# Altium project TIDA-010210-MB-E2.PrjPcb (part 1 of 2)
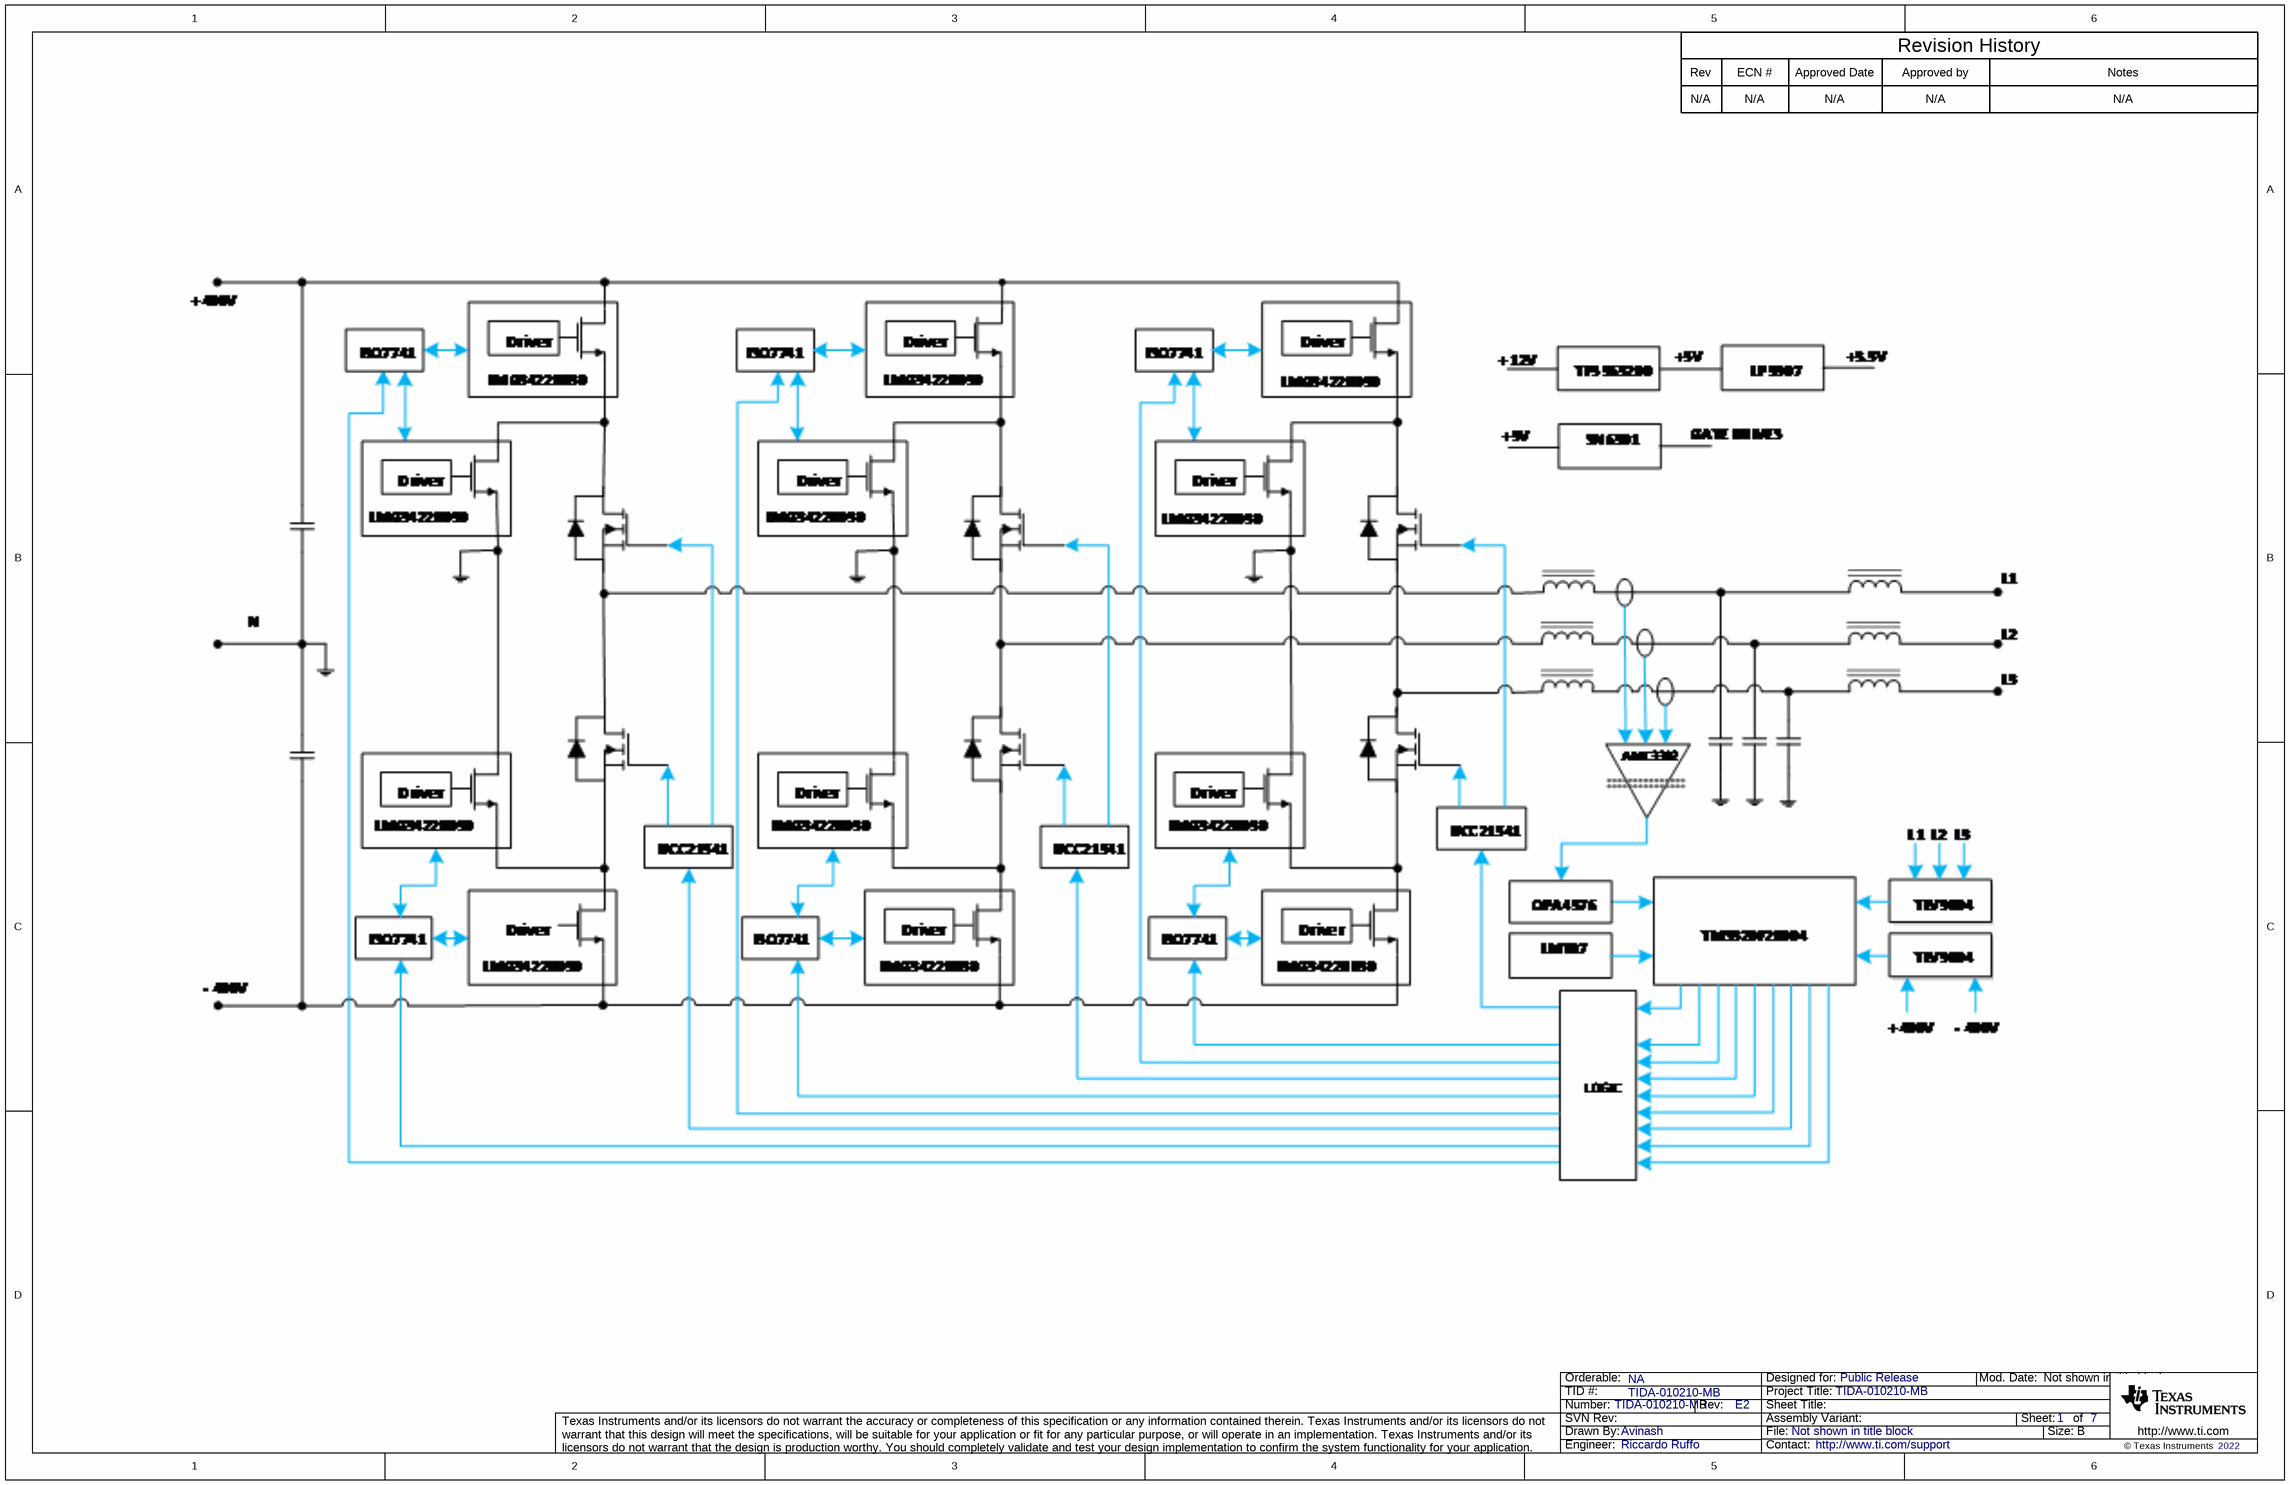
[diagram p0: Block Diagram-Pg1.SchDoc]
TID: TIDA-010210-MB; TechSupport: http://www.ti.com/support; SCH_Rev: E2; PRJ_Title: TIDA-010210-MB; PRJ_Number: TIDA-010210-MB; PRJ_Engineer: Riccardo Ruffo; PRJ_Customer: Public Release; PCB_Rev: E2; PCB_Layout: Riccardo Ruffo; EVM_Orderable: NA; CopyrightYear: 2022
7 sheets, 474 parts. Net scope: global (net labels, ports and power ports of the same name join across sheets).
Board file: TIDA-010210-MB-E2.PcbDoc
Sheets:
  Block Diagram-Pg1.SchDoc
  Power Stage-Pg2.SchDoc
  Power Supply and Protection-Pg3.SchDoc
  Voltage Sensing-Pg4.SchDoc
  Current Sensing-Pg5.SchDoc
  Controller Card-Pg6.SchDoc
  Hardware-Pg7.SchDoc

## Sheet Block Diagram-Pg1.SchDoc
size 431 x 279 mm; Date: Not shown in title block; ApprovedBy: Not shown in title block; CheckedBy: Not shown in title block; Author: Not shown in title block; CompanyName: Not shown in title block; DrawnBy: Avinash; Engineer: Not shown in title block; Organization: Not shown in title block; Address1: Not shown in title block; Address2: Not shown in title block; Address3: Not shown in title block; Address4: Not shown in title block; DocumentNumber: 1; Revision: Use project parameter SCH_Rev; SheetNumber: 1; SheetTotal: 7; PageSetup: Record=PageOptions¦CenterHorizontal=True¦CenterVertical=True¦PrintScale=1.00¦XCorrection=1.00¦YCorrection=1.00¦PrintKind=0¦BorderSize=5000000¦LeftOffset=0¦BottomOffset=0¦Orientation=2¦PaperLength=1000¦PaperWidth=1000¦Scale=100¦PaperSource=15¦PrintQuality=600¦MediaType=1¦DitherType=10¦PaperKind=Letter¦PrintScaleMode=1

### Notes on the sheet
- Rev
- N/A
- ECN #
- Approved Date
- Approved by
- Revision History
- Notes

## Sheet Power Stage-Pg2.SchDoc
size 431 x 279 mm; Date: Not shown in title block; ApprovedBy: Not shown in title block; CheckedBy: Not shown in title block; Author: Not shown in title block; CompanyName: Not shown in title block; DrawnBy: Avinash; Engineer: Not shown in title block; Organization: Not shown in title block; Address1: Not shown in title block; Address2: Not shown in title block; Address3: Not shown in title block; Address4: Not shown in title block; DocumentNumber: 1; Revision: Use project parameter SCH_Rev; SheetNumber: 2; SheetTotal: 7; PageSetup: Record=PageOptions¦CenterHorizontal=True¦CenterVertical=True¦PrintScale=1.00¦XCorrection=1.00¦YCorrection=1.00¦PrintKind=0¦BorderSize=5000000¦LeftOffset=0¦BottomOffset=0¦Orientation=2¦PaperLength=1000¦PaperWidth=1000¦Scale=100¦PaperSource=15¦PrintQuality=600¦MediaType=1¦DitherType=10¦PaperKind=Letter¦PrintScaleMode=1
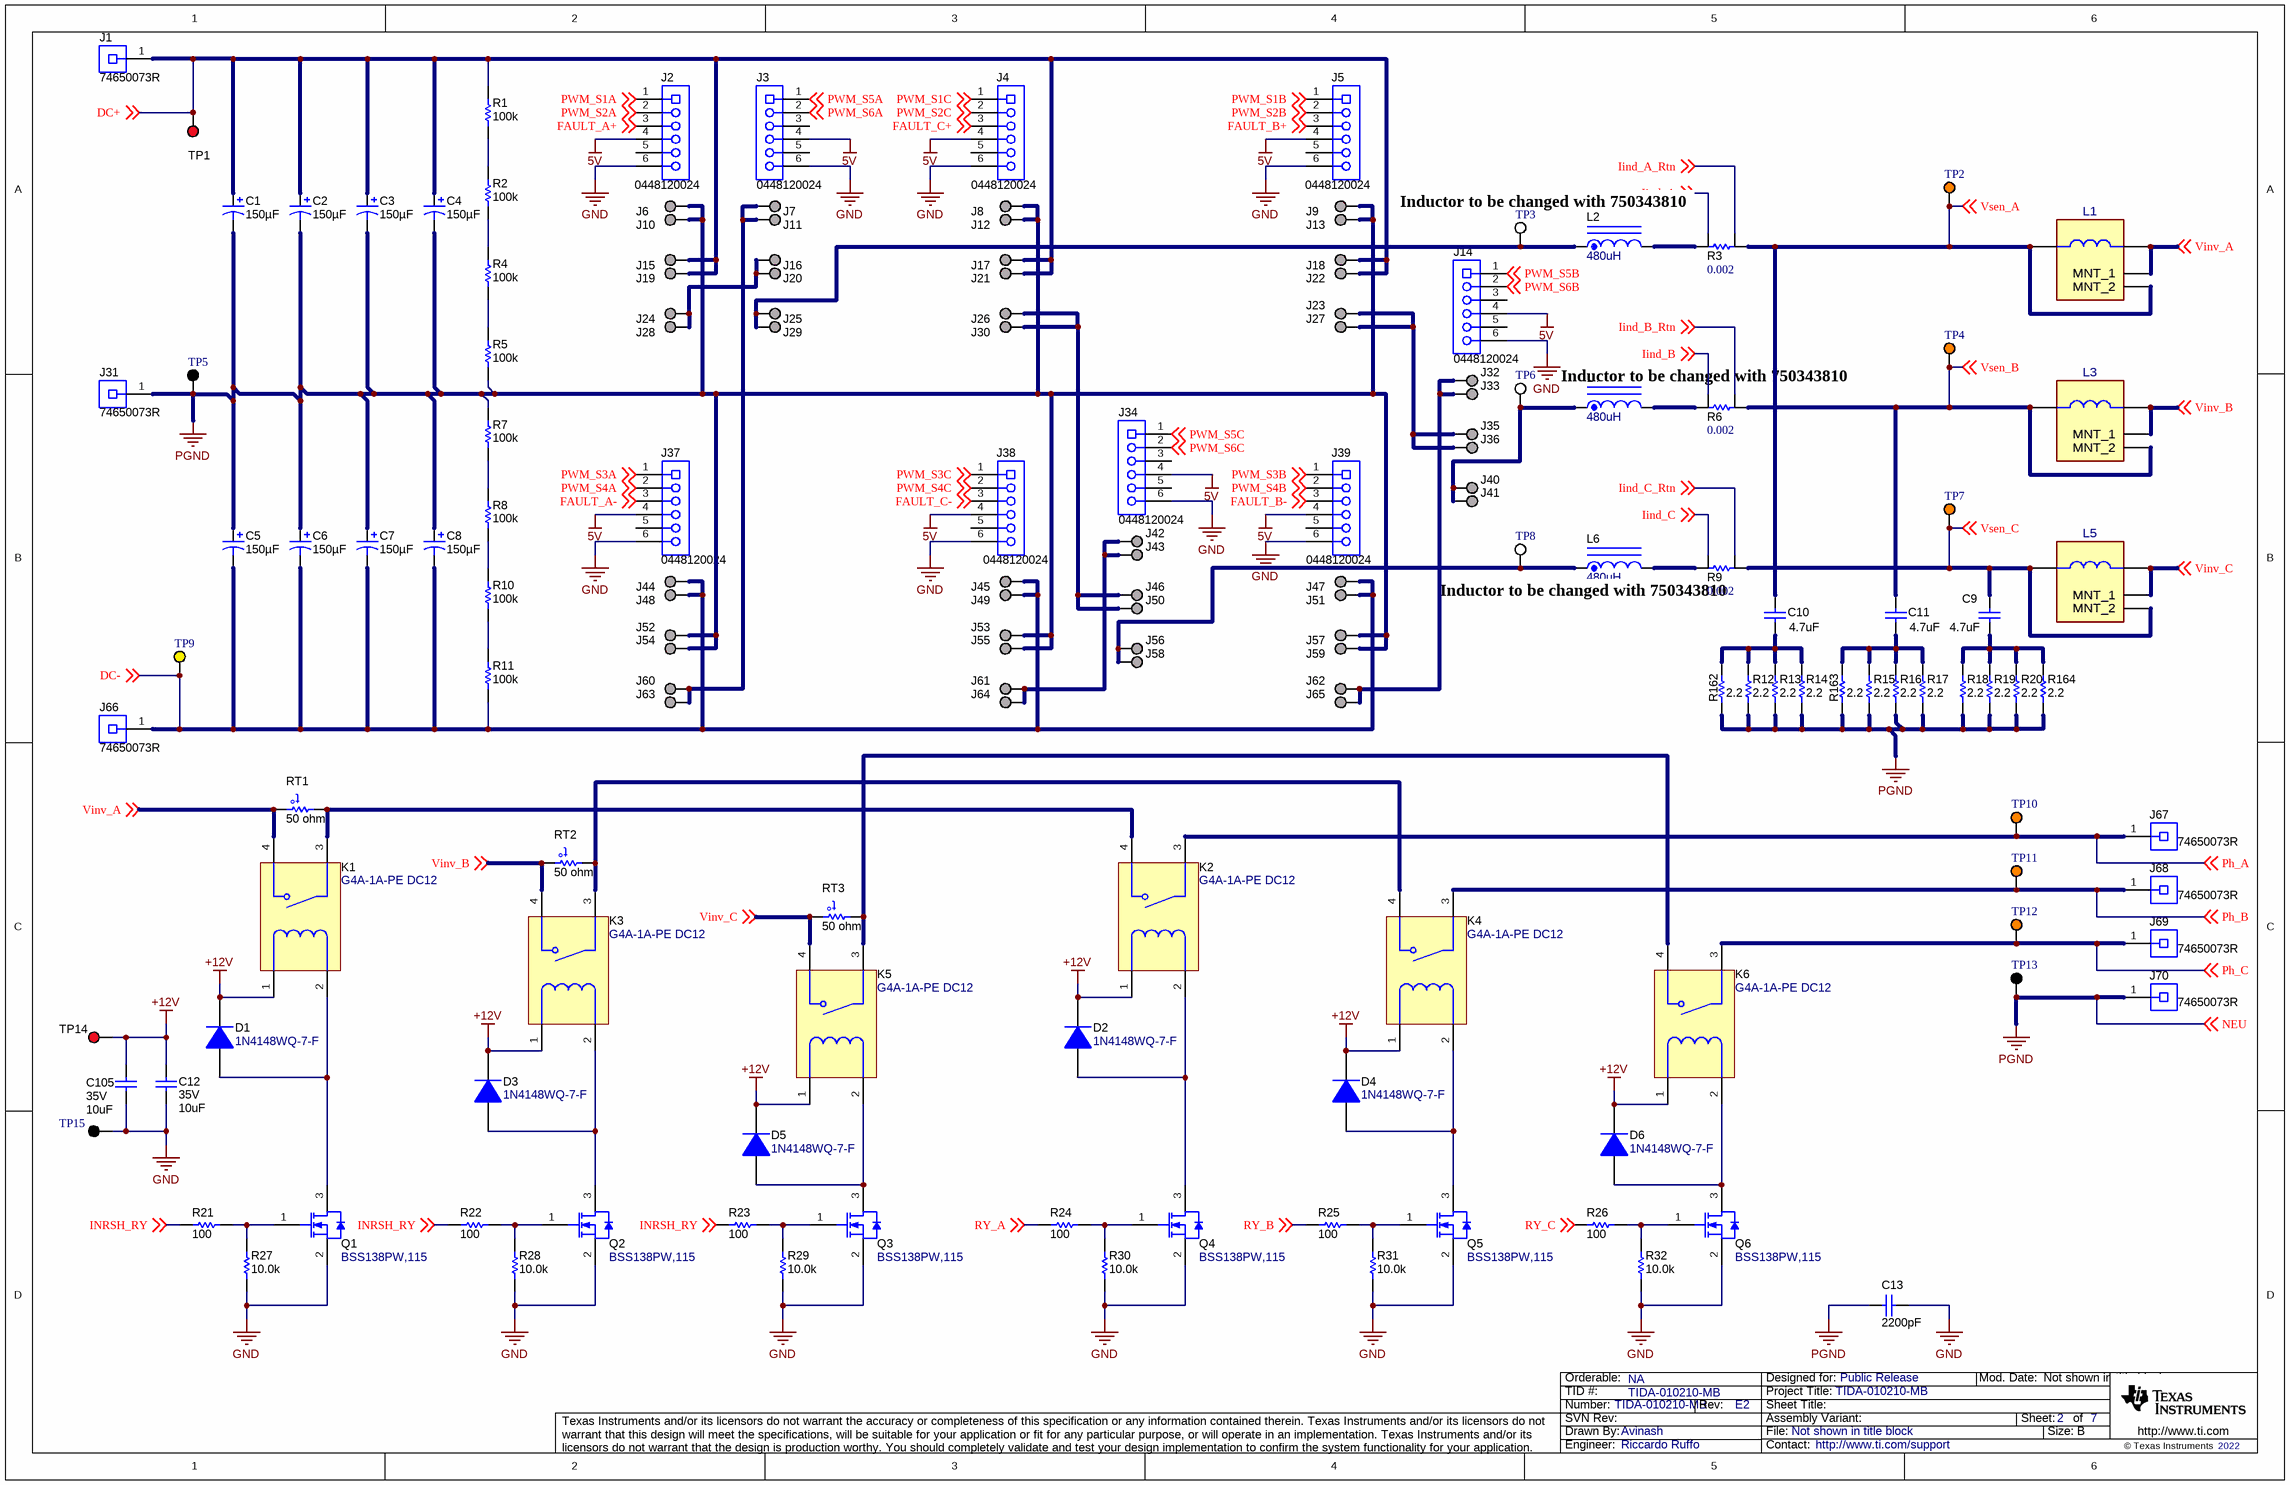
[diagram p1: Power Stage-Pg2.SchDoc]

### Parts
C1  ValueDisplayed: 150µF  [ESG157M500AQ5]  (hidden comment: ESG157M500AQ5)
C2  ValueDisplayed: 150µF  [ESG157M500AQ5]  (hidden comment: ESG157M500AQ5)
C3  ValueDisplayed: 150µF  [ESG157M500AQ5]  (hidden comment: ESG157M500AQ5)
C4  ValueDisplayed: 150µF  [ESG157M500AQ5]  (hidden comment: ESG157M500AQ5)
C5  ValueDisplayed: 150µF  [ESG157M500AQ5]  (hidden comment: ESG157M500AQ5)
C6  ValueDisplayed: 150µF  [ESG157M500AQ5]  (hidden comment: ESG157M500AQ5)
C7  ValueDisplayed: 150µF  [ESG157M500AQ5]  (hidden comment: ESG157M500AQ5)
C8  ValueDisplayed: 150µF  [ESG157M500AQ5]  (hidden comment: ESG157M500AQ5)
C9  ValueDisplayed: 4.7uF  [B32924_31mm]  (hidden comment: B32924D3475K)
C10  ValueDisplayed: 4.7uF  [B32924_31mm]  (hidden comment: B32924D3475K)
C11  ValueDisplayed: 4.7uF  [B32924_31mm]  (hidden comment: B32924D3475K)
C12  VDC_V: 35V  ValueDisplayed: 10uF  [1206_190]  (hidden comment: CGA5L1X7R1V106K160AC)
C13  ValueDisplayed: 2200pF  [VY1_1200x500_V]  (hidden comment: VY1222K47Y5UQ6TVX)
C105  VDC_V: 35V  ValueDisplayed: 10uF  [1206_190]  (hidden comment: CGA5L1X7R1V106K160AC)
D1  1N4148WQ-7-F  [SOD-123]
D2  1N4148WQ-7-F  [SOD-123]
D3  1N4148WQ-7-F  [SOD-123]
D4  1N4148WQ-7-F  [SOD-123]
D5  1N4148WQ-7-F  [SOD-123]
D6  1N4148WQ-7-F  [SOD-123]
J1  74650073R  [Wurth_WP-THRBU]
J2  0448120024  [Molex_0448120024]
J3  0448120024  [Molex_0448120024]
J4  0448120024  [Molex_0448120024]
J5  0448120024  [Molex_0448120024]
J6  Suggest using a net name here  [Mill-Max_0312-0-15-15-34-27-10-0]  (value not drawn)
J7  Suggest using a net name here  [Mill-Max_0312-0-15-15-34-27-10-0]  (value not drawn)
J8  Suggest using a net name here  [Mill-Max_0312-0-15-15-34-27-10-0]  (value not drawn)
J9  Suggest using a net name here  [Mill-Max_0312-0-15-15-34-27-10-0]  (value not drawn)
J10  Suggest using a net name here  [Mill-Max_0312-0-15-15-34-27-10-0]  (value not drawn)
J11  Suggest using a net name here  [Mill-Max_0312-0-15-15-34-27-10-0]  (value not drawn)
J12  Suggest using a net name here  [Mill-Max_0312-0-15-15-34-27-10-0]  (value not drawn)
J13  Suggest using a net name here  [Mill-Max_0312-0-15-15-34-27-10-0]  (value not drawn)
J14  0448120024  [Molex_0448120024]
J15  Suggest using a net name here  [Mill-Max_0312-0-15-15-34-27-10-0]  (value not drawn)
J16  Suggest using a net name here  [Mill-Max_0312-0-15-15-34-27-10-0]  (value not drawn)
J17  Suggest using a net name here  [Mill-Max_0312-0-15-15-34-27-10-0]  (value not drawn)
J18  Suggest using a net name here  [Mill-Max_0312-0-15-15-34-27-10-0]  (value not drawn)
J19  Suggest using a net name here  [Mill-Max_0312-0-15-15-34-27-10-0]  (value not drawn)
J20  Suggest using a net name here  [Mill-Max_0312-0-15-15-34-27-10-0]  (value not drawn)
J21  Suggest using a net name here  [Mill-Max_0312-0-15-15-34-27-10-0]  (value not drawn)
J22  Suggest using a net name here  [Mill-Max_0312-0-15-15-34-27-10-0]  (value not drawn)
J23  Suggest using a net name here  [Mill-Max_0312-0-15-15-34-27-10-0]  (value not drawn)
J24  Suggest using a net name here  [Mill-Max_0312-0-15-15-34-27-10-0]  (value not drawn)
J25  Suggest using a net name here  [Mill-Max_0312-0-15-15-34-27-10-0]  (value not drawn)
J26  Suggest using a net name here  [Mill-Max_0312-0-15-15-34-27-10-0]  (value not drawn)
J27  Suggest using a net name here  [Mill-Max_0312-0-15-15-34-27-10-0]  (value not drawn)
J28  Suggest using a net name here  [Mill-Max_0312-0-15-15-34-27-10-0]  (value not drawn)
J29  Suggest using a net name here  [Mill-Max_0312-0-15-15-34-27-10-0]  (value not drawn)
J30  Suggest using a net name here  [Mill-Max_0312-0-15-15-34-27-10-0]  (value not drawn)
J31  74650073R  [Wurth_WP-THRBU]
J32  Suggest using a net name here  [Mill-Max_0312-0-15-15-34-27-10-0]  (value not drawn)
J33  Suggest using a net name here  [Mill-Max_0312-0-15-15-34-27-10-0]  (value not drawn)
J34  0448120024  [Molex_0448120024]
J35  Suggest using a net name here  [Mill-Max_0312-0-15-15-34-27-10-0]  (value not drawn)
J36  Suggest using a net name here  [Mill-Max_0312-0-15-15-34-27-10-0]  (value not drawn)
J37  0448120024  [Molex_0448120024]
J38  0448120024  [Molex_0448120024]
J39  0448120024  [Molex_0448120024]
J40  Suggest using a net name here  [Mill-Max_0312-0-15-15-34-27-10-0]  (value not drawn)
J41  Suggest using a net name here  [Mill-Max_0312-0-15-15-34-27-10-0]  (value not drawn)
J42  Suggest using a net name here  [Mill-Max_0312-0-15-15-34-27-10-0]  (value not drawn)
J43  Suggest using a net name here  [Mill-Max_0312-0-15-15-34-27-10-0]  (value not drawn)
J44  Suggest using a net name here  [Mill-Max_0312-0-15-15-34-27-10-0]  (value not drawn)
J45  Suggest using a net name here  [Mill-Max_0312-0-15-15-34-27-10-0]  (value not drawn)
J46  Suggest using a net name here  [Mill-Max_0312-0-15-15-34-27-10-0]  (value not drawn)
J47  Suggest using a net name here  [Mill-Max_0312-0-15-15-34-27-10-0]  (value not drawn)
J48  Suggest using a net name here  [Mill-Max_0312-0-15-15-34-27-10-0]  (value not drawn)
J49  Suggest using a net name here  [Mill-Max_0312-0-15-15-34-27-10-0]  (value not drawn)
J50  Suggest using a net name here  [Mill-Max_0312-0-15-15-34-27-10-0]  (value not drawn)
J51  Suggest using a net name here  [Mill-Max_0312-0-15-15-34-27-10-0]  (value not drawn)
J52  Suggest using a net name here  [Mill-Max_0312-0-15-15-34-27-10-0]  (value not drawn)
J53  Suggest using a net name here  [Mill-Max_0312-0-15-15-34-27-10-0]  (value not drawn)
J54  Suggest using a net name here  [Mill-Max_0312-0-15-15-34-27-10-0]  (value not drawn)
J55  Suggest using a net name here  [Mill-Max_0312-0-15-15-34-27-10-0]  (value not drawn)
J56  Suggest using a net name here  [Mill-Max_0312-0-15-15-34-27-10-0]  (value not drawn)
J57  Suggest using a net name here  [Mill-Max_0312-0-15-15-34-27-10-0]  (value not drawn)
J58  Suggest using a net name here  [Mill-Max_0312-0-15-15-34-27-10-0]  (value not drawn)
J59  Suggest using a net name here  [Mill-Max_0312-0-15-15-34-27-10-0]  (value not drawn)
J60  Suggest using a net name here  [Mill-Max_0312-0-15-15-34-27-10-0]  (value not drawn)
J61  Suggest using a net name here  [Mill-Max_0312-0-15-15-34-27-10-0]  (value not drawn)
J62  Suggest using a net name here  [Mill-Max_0312-0-15-15-34-27-10-0]  (value not drawn)
J63  Suggest using a net name here  [Mill-Max_0312-0-15-15-34-27-10-0]  (value not drawn)
J64  Suggest using a net name here  [Mill-Max_0312-0-15-15-34-27-10-0]  (value not drawn)
J65  Suggest using a net name here  [Mill-Max_0312-0-15-15-34-27-10-0]  (value not drawn)
J66  74650073R  [Wurth_WP-THRBU]
J67  74650073R  [Wurth_WP-THRBU]
J68  74650073R  [Wurth_WP-THRBU]
J69  74650073R  [Wurth_WP-THRBU]
J70  74650073R  [Wurth_WP-THRBU]
K1  G4A-1A-PE DC12  [RELAY_G4A-1A-PE]
K2  G4A-1A-PE DC12  [RELAY_G4A-1A-PE]
K3  G4A-1A-PE DC12  [RELAY_G4A-1A-PE]
K4  G4A-1A-PE DC12  [RELAY_G4A-1A-PE]
K5  G4A-1A-PE DC12  [RELAY_G4A-1A-PE]
K6  G4A-1A-PE DC12  [RELAY_G4A-1A-PE]
L1  7443783533220  [FP-7443783533220_PTH_34MM5_36MM-MFG]  (value not drawn)
L2  ValueDisplayed: 480uH  [750344413]  (hidden comment: 750344413)
L3  7443783533220  [FP-7443783533220_PTH_34MM5_36MM-MFG]  (value not drawn)
L4  ValueDisplayed: 480uH  [750344413]  (hidden comment: 750344413)
L5  7443783533220  [FP-7443783533220_PTH_34MM5_36MM-MFG]  (value not drawn)
L6  ValueDisplayed: 480uH  [750344413]  (hidden comment: 750344413)
Q1  BSS138PW,115  [SOT-323]
Q2  BSS138PW,115  [SOT-323]
Q3  BSS138PW,115  [SOT-323]
Q4  BSS138PW,115  [SOT-323]
Q5  BSS138PW,115  [SOT-323]
Q6  BSS138PW,115  [SOT-323]
R1  ValueDisplayed: 100k  [1206]  (hidden comment: RC1206FR-07100KL)
R2  ValueDisplayed: 100k  [1206]  (hidden comment: RC1206FR-07100KL)
R3  ValueDisplayed: 0.002  [WSL4026_310]  (hidden comment: WSL40262L000FEB)
R4  ValueDisplayed: 100k  [1206]  (hidden comment: RC1206FR-07100KL)
R5  ValueDisplayed: 100k  [1206]  (hidden comment: RC1206FR-07100KL)
R6  ValueDisplayed: 0.002  [WSL4026_310]  (hidden comment: WSL40262L000FEB)
R7  ValueDisplayed: 100k  [1206]  (hidden comment: RC1206FR-07100KL)
R8  ValueDisplayed: 100k  [1206]  (hidden comment: RC1206FR-07100KL)
R9  ValueDisplayed: 0.002  [WSL4026_310]  (hidden comment: WSL40262L000FEB)
R10  ValueDisplayed: 100k  [1206]  (hidden comment: RC1206FR-07100KL)
R11  ValueDisplayed: 100k  [1206]  (hidden comment: RC1206FR-07100KL)
R12  ValueDisplayed: 2.2  [2512]  (hidden comment: 35222R2JT)
R13  ValueDisplayed: 2.2  [2512]  (hidden comment: 35222R2JT)
R14  ValueDisplayed: 2.2  [2512]  (hidden comment: 35222R2JT)
R15  ValueDisplayed: 2.2  [2512]  (hidden comment: 35222R2JT)
R16  ValueDisplayed: 2.2  [2512]  (hidden comment: 35222R2JT)
R17  ValueDisplayed: 2.2  [2512]  (hidden comment: 35222R2JT)
R18  ValueDisplayed: 2.2  [2512]  (hidden comment: 35222R2JT)
R19  ValueDisplayed: 2.2  [2512]  (hidden comment: 35222R2JT)
R20  ValueDisplayed: 2.2  [2512]  (hidden comment: 35222R2JT)
R21  ValueDisplayed: 100  [0603]  (hidden comment: ESR03EZPJ101)
R22  ValueDisplayed: 100  [0603]  (hidden comment: ESR03EZPJ101)
R23  ValueDisplayed: 100  [0603]  (hidden comment: ESR03EZPJ101)
R24  ValueDisplayed: 100  [0603]  (hidden comment: ESR03EZPJ101)
R25  ValueDisplayed: 100  [0603]  (hidden comment: ESR03EZPJ101)
R26  ValueDisplayed: 100  [0603]  (hidden comment: ESR03EZPJ101)
R27  ValueDisplayed: 10.0k  [0603]  (hidden comment: ERJ-3EKF1002V)
R28  ValueDisplayed: 10.0k  [0603]  (hidden comment: ERJ-3EKF1002V)
R29  ValueDisplayed: 10.0k  [0603]  (hidden comment: ERJ-3EKF1002V)
R30  ValueDisplayed: 10.0k  [0603]  (hidden comment: ERJ-3EKF1002V)
R31  ValueDisplayed: 10.0k  [0603]  (hidden comment: ERJ-3EKF1002V)
R32  ValueDisplayed: 10.0k  [0603]  (hidden comment: ERJ-3EKF1002V)
R162  ValueDisplayed: 2.2  [2512]  (hidden comment: 35222R2JT)
R163  ValueDisplayed: 2.2  [2512]  (hidden comment: 35222R2JT)
R164  ValueDisplayed: 2.2  [2512]  (hidden comment: 35222R2JT)
RT1  value 50 ohm  [TDK_B751]  (hidden comment: B59751B0120A070)
RT2  value 50 ohm  [TDK_B751]  (hidden comment: B59751B0120A070)
RT3  value 50 ohm  [TDK_B751]  (hidden comment: B59751B0120A070)
TP1  5000  [Keystone5000]  (value not drawn)
TP2  5003  [Keystone5003]  (value not drawn)
TP3  5002  [Keystone5002]  (value not drawn)
TP4  5003  [Keystone5003]  (value not drawn)
TP5  5001  [Keystone5001]  (value not drawn)
TP6  5002  [Keystone5002]  (value not drawn)
TP7  5003  [Keystone5003]  (value not drawn)
TP8  5002  [Keystone5002]  (value not drawn)
TP9  5004  [Keystone5004]  (value not drawn)
TP10  5003  [Keystone5003]  (value not drawn)
TP11  5003  [Keystone5003]  (value not drawn)
TP12  5003  [Keystone5003]  (value not drawn)
TP13  5001  [Keystone5001]  (value not drawn)
TP14  5000  [Keystone5000]  (value not drawn)
TP15  5001  [Keystone5001]  (value not drawn)

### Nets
5V: J2.4 J3.4 J4.4 J5.4 J14.4 J34.4 J37.4 J38.4 J39.4
+12V: C12.1 C105.1 D1.1(K) D2.1(K) D3.1(K) D4.1(K) D5.1(K) D6.1(K) K1.1 K2.1 K3.1 K4.1 K5.1 K6.1 TP14.1
GND: C12.2 C13.1 C105.2 J2.6 J3.6 J4.6 J5.6 J14.6 J34.6 J37.6 J38.6 J39.6 Q1.2(S) Q2.2(S) Q3.2(S) Q4.2(S) Q5.2(S) Q6.2(S) R27.1 R28.1 R29.1 R30.1 R31.1 R32.1 TP15.1
PGND: C1.2(-) C2.2(-) C3.2(-) C4.2(-) C5.1(+) C6.1(+) C7.1(+) C8.1(+) C13.2 J6.1 J8.1 J9.1 J10.1 J12.1 J13.1 J31.1 J52.1 J53.1 J54.1 J55.1 J57.1 J59.1 J70.1 R5.1 R7.2 R12.1 R13.1 R14.1 R15.1 R16.1 R17.1 R18.1 R19.1 R20.1 R162.1 R163.1 R164.1 TP5.1 TP13.1 ; off-sheet NEU  [also labelled NEU]
DC+: C1.1(+) C2.1(+) C3.1(+) C4.1(+) J1.1 J15.1 J17.1 J18.1 J19.1 J21.1 J22.1 R1.2 TP1.1 ; off-sheet DC+
DC-: C5.2(-) C6.2(-) C7.2(-) C8.2(-) J44.1 J45.1 J47.1 J48.1 J49.1 J51.1 J66.1 R11.1 TP9.1 ; off-sheet DC-
FAULT_A+: J2.3 ; off-sheet FAULT_A+
FAULT_A-: J37.3 ; off-sheet FAULT_A-
FAULT_B+: J5.3 ; off-sheet FAULT_B+
FAULT_B-: J39.3 ; off-sheet FAULT_B-
FAULT_C+: J4.3 ; off-sheet FAULT_C+
FAULT_C-: J38.3 ; off-sheet FAULT_C-
Iind_A: R3.3 ; off-sheet Iind_A
Iind_A_Rtn: R3.4 ; off-sheet Iind_A_Rtn
Iind_B: R6.3 ; off-sheet Iind_B
Iind_B_Rtn: R6.4 ; off-sheet Iind_B_Rtn
Iind_C: R9.3 ; off-sheet Iind_C
Iind_C_Rtn: R9.4 ; off-sheet Iind_C_Rtn
INRSH_RY: R21.1 R22.1 R23.1 ; off-sheet INRSH_RY
Ph_A: J67.1 K2.3 TP10.1 ; off-sheet Ph_A
Ph_B: J68.1 K4.3 TP11.1 ; off-sheet Ph_B
Ph_C: J69.1 K6.3 TP12.1 ; off-sheet Ph_C
PWM_S1A: J2.1 ; off-sheet PWM_S1A
PWM_S1B: J5.1 ; off-sheet PWM_S1B
PWM_S1C: J4.1 ; off-sheet PWM_S1C
PWM_S2A: J2.2 ; off-sheet PWM_S2A
PWM_S2B: J5.2 ; off-sheet PWM_S2B
PWM_S2C: J4.2 ; off-sheet PWM_S2C
PWM_S3A: J37.1 ; off-sheet PWM_S3A
PWM_S3B: J39.1 ; off-sheet PWM_S3B
PWM_S3C: J38.1 ; off-sheet PWM_S3C
PWM_S4A: J37.2 ; off-sheet PWM_S4A
PWM_S4B: J39.2 ; off-sheet PWM_S4B
PWM_S4C: J38.2 ; off-sheet PWM_S4C
PWM_S5A: J3.1 ; off-sheet PWM_S5A
PWM_S5B: J14.1 ; off-sheet PWM_S5B
PWM_S5C: J34.1 ; off-sheet PWM_S5C
PWM_S6A: J3.2 ; off-sheet PWM_S6A
PWM_S6B: J14.2 ; off-sheet PWM_S6B
PWM_S6C: J34.2 ; off-sheet PWM_S6C
RY_A: R24.1 ; off-sheet RY_A
RY_B: R25.1 ; off-sheet RY_B
RY_C: R26.1 ; off-sheet RY_C
Vinv_A: K1.4 L1.2 L1.3(MNT_1) RT1.2 ; off-sheet Vinv_A
Vinv_B: K3.4 L3.2 L3.3(MNT_1) RT2.2 ; off-sheet Vinv_B
Vinv_C: K5.4 L5.2 L5.3(MNT_1) RT3.2 ; off-sheet Vinv_C
Vsen_A: C10.1 L1.1 L1.4(MNT_2) R3.2 TP2.1 ; off-sheet Vsen_A
Vsen_B: C11.1 L3.1 L3.4(MNT_2) R6.2 TP4.1 ; off-sheet Vsen_B
Vsen_C: C9.1 L5.1 L5.4(MNT_2) R9.2 TP7.1 ; off-sheet Vsen_C
NetC9_2: C9.2 R18.2 R19.2 R20.2 R164.2
NetC10_2: C10.2 R12.2 R13.2 R14.2 R162.2
NetC11_2: C11.2 R15.2 R16.2 R17.2 R163.2
NetD1_2: D1.2(A) K1.2 Q1.3(D)
NetD2_2: D2.2(A) K2.2 Q4.3(D)
NetD3_2: D3.2(A) K3.2 Q2.3(D)
NetD4_2: D4.2(A) K4.2 Q5.3(D)
NetD5_2: D5.2(A) K5.2 Q3.3(D)
NetD6_2: D6.2(A) K6.2 Q6.3(D)
NetJ7_1: J7.1 J11.1 J60.1 J63.1
NetJ16_1: J16.1 J20.1 J24.1 J28.1
NetJ23_1: J23.1 J27.1 J35.1 J36.1
NetJ25_1: J25.1 J29.1 L2.1 TP3.1
NetJ26_1: J26.1 J30.1 J46.1 J50.1
NetJ32_1: J32.1 J33.1 J62.1 J65.1
NetJ40_1: J40.1 J41.1 L4.1 TP6.1
NetJ42_1: J42.1 J43.1 J61.1 J64.1
NetJ56_1: J56.1 J58.1 L6.1 TP8.1
NetK1_3: K1.3 K2.4 RT1.1
NetK3_3: K3.3 K4.4 RT2.1
NetK5_3: K5.3 K6.4 RT3.1
NetL2_2: L2.2 R3.1
NetL4_2: L4.2 R6.1
NetL6_2: L6.2 R9.1
NetQ1_1: Q1.1(G) R21.2 R27.2
NetQ2_1: Q2.1(G) R22.2 R28.2
NetQ3_1: Q3.1(G) R23.2 R29.2
NetQ4_1: Q4.1(G) R24.2 R30.2
NetQ5_1: Q5.1(G) R25.2 R31.2
NetQ6_1: Q6.1(G) R26.2 R32.2
NetR1_1: R1.1 R2.2
NetR2_1: R2.1 R4.2
NetR4_1: R4.1 R5.2
NetR7_1: R7.1 R8.2
NetR8_1: R8.1 R10.2
NetR10_1: R10.1 R11.2

Not connected (* = marked no-connect by the designer): J2 5; J3 3 5; J4 5; J5 5; J14 3 5; J34 3 5; J37 5; J38 5; J39 5

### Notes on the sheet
- Inductor to be changed with 750343810

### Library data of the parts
C1-C8 = LGN2X121MELB45: CAP, AL, 150 uF, 550 V, +/- 20%, TH; Manufacturer: Kemet; Polarized: Y; CompType: Capacitor; Value: 150uF; U/M: EA; Tolerance_%: 20; VDC_V: 550; Value2: 550V; TaMin_C: -25; TaMax_C: 105; Cap_Case: 22x45mm; SizeX_mm: 22; SizeZ_mm: 45; AEC Category: Q200; AEC Qualified: N
C9-C11 = CMP-0012442-3: CAP, Film, 4.7 uF, 630 V, +/- 10%, 0.015 ohm, TH; Manufacturer: TDK; ESR_ohm: 0.015; Polarized: N; SizeAreaWB_mm2: 770.5; Value: 4.7uF; TaMax_C: 110°C; SizeZ_mm: 31; SizeX_mm: 21; SizeY_mm: 31.5; Value2: 630V; SizeArea_mm2: 661.5; Cap_F: 4.7µF; IRMS_A: 457mA; AEC Category: Q200
C12 C105 = CMP-0008772-2: CAP, CERM, 10 uF, 35 V, +/- 10%, X7R, AEC-Q200 Grade 1, 1206_190; Manufacturer: TDK; TaMin_C: -55°C; ESR_ohm: 2.229m; Polarized: N; SizeAreaWB_mm2: 10.92; Value1: 0.002229 ohm; U/M: EA; Value: 10uF; TaMax_C: 125°C; SizeZ_mm: 1.9; SizeX_mm: 3.2; SizeY_mm: 1.6; SizeArea_mm2: 5.12; AEC Qualified: Y; Cap_F: 10µF; IRMS_A: 4.85932A; AEC Grade: 1; AEC Category: Q200
C13 = CMP-0064961-1: CAP, CERM, 2200 pF, X1 760 VAC/Y1 500 VAC, +/- 10%, Y5U, D12xT5mm; Manufacturer: Vishay-Bccomponents; TaMin_C: -40°C; AC_Safety: X1Y1; Polarized: N; SizeAreaWB_mm2: 98; Value1: Unknown; U/M: EA; Value: 2200pF; TaMax_C: 125°C; VAC_Y: 500; VAC_X: 760; SizeZ_mm: 16; SizeX_mm: 12; SizeY_mm: 5; Cap_Case: 12x5mm; Value2: V; SizeArea_mm2: 60; Cap_F: 2.2nF; AEC Category: Q200
D1-D6 = CMP-0750148-1: Diode, Switching, 100 V, 0.3 A, AEC-Q101, SOD-123; Manufacturer: Diodes Inc.; Value2: 1.25V; TJmax_C: 150°C; AEC Category: Q101; Value: 100V; SizeAreaWB_mm2: 13.095; SizeArea_mm2: 6.545; SizeX_mm: 3.85; AEC Qualified: Y; Io_A: 300mA; Value1: 0.3A; SizeZ_mm: 1.35; SizeY_mm: 1.7
J1 J31 J66-J70 = CMP-0078526-1: Power Element Bush, M3, TH; Manufacturer: Wurth Elektronik; Gender: Female; Current_A: 50A; ContactFinish: Tin; CompType: Screw Terminal
J2-J5 J14 J34 J37-J39 = 0448120024: Receptacle, 2.54mm, 6x1, Gold, TH; Manufacturer: Molex; SymbolCreator: a0411947; U/M: EA
J6-J13 J15-J30 J32 J33 J35 J36 J40-J65 = 0312-0-15-15-34-27-10-0: Pin Receptacle, .032-.046" .075" Dia, Gold, TH; Manufacturer: Mill-Max; U/M: EA
K1-K6 = CMP-0002594-2: Relay, SPST-NO (1 Form A), 20 A, 12 V, TH; Manufacturer: Omron Electronic Components; Contact Rating_A: 20A; Turn On Voltage (Max)_VDC: 8.4V; Coil Power_W: 900mW; Coil Resistance_ohm: 160; Time Operate (s): 20ms; Coil Current_A: 75mA; Turn Off Voltage (Min)_VDC: 1.2V; Coil Type: Non Latching; Time Release (s): 10ms; Coil Voltage_VDC: 12V
L1 L3 L5 = CMP-0087414-1: IND 22uH TOL 20%; Manufacturer: Wurth Electronics; Isat: 49.4A; DCR_ohm: 8.8m; Irms: 23.2A; Material: Manganese Zinc Ferrite; SizeZ_mm: 35mm; AEC Qualified: No; Ind_H: 22µH
L2 L4 L6 = G154017LF: Inductor, 480uH, 15 A, 0.060 ohm, TH; Manufacturer: Wurth Elektronik; SymbolCreator: a0412235; Imax_A: 15A; DCR_ohm: 0.060; SizeX_mm: 36; SizeY_mm: 40; AEC Category: Q200; AEC Qualified: N
Q1-Q6 = CMP-0000790-2: MOSFET, N-CH, 60 V, 0.32 A, AEC-Q101, SOT-323; Alternate Manufacturer: None; Manufacturer: Nexperia; SizeZ_mm: 1.1; ChType: N; Value2: 0.72 nC; VdsMax_V: 60V; SizeX_mm: 2.2; Vgs_V: 20V; QgTyp_nC: 0.72; AEC Qualified: Y; Value: 60V; SizeArea_mm2: 4.84; AEC Category: Q101; IdsMax_A: 320mA; SizeAreaWB_mm2: 10.24
R1 R2 R4 R5 R7 R8 R10 R11 = CMP-0017836-2: RES, 100 k, 1%, 0.25 W, 1206; Manufacturer: Yageo America; Power_W: 250mW; TempCo: 100 ppm/C; U/M: EA; Value: 100k; EIA_Code: E96; SizeX_mm: 3.2; SizeY_mm: 1.6; SizeZ_mm: 1.35; Value2: 0.25W; SizeArea_mm2: 5.12; VDC_V: 200V; AEC Category: Q200
R3 R6 R9 = CMP-0015295-2: RES, 0.002, 1%, 3 W, AEC-Q200 Grade 0, 4026; Manufacturer: Vishay-Dale; Power_W: 3W; TempCo: 75 ppm/C; Value_Code: 2L000; U/M: EA; Value: 0.002; Res_ohm: 2m; CompType: Resistor; AEC Qualified: Y; AEC Grade: 0; AEC Category: Q200
R12-R20 R162-R164 = CMP-0015862-2: RES, 2.2, 5%, 3 W, 2512; Manufacturer: TE Connectivity; Power_W: 3W; TempCo: ppm/C; Value_Code: 2R20; U/M: EA; Value: 2.2; EIA_Code: E24; SizeX_mm: 6.3; SizeY_mm: 3.2; SizeZ_mm: 0.71; SizeArea_mm2: 20.16; AEC Qualified: N; AEC Category: Q200
R21-R26 = CMP-0025882-3: RES, 100, 5%, 0.25 W, AEC-Q200 Grade 0, 0603; Manufacturer: Rohm; Value: 100; Value_Code: 100R; Power_W: 250mW; Value2: 0.25W; VDC_V: 150V; TempCo: 200 ppm/C; SizeArea_mm2: 1.28; SizeX_mm: 1.6; SizeY_mm: 0.8; SizeZ_mm: 1; EIA_Code: E24; AEC Category: Q200; AEC Qualified: Y; AEC Grade: 0; U/M: EA
R27-R32 = CMP-0022684-3: RES, 10.0 k, 1%, 0.1 W, 0603; Manufacturer: Panasonic; Value: 10.0k; Res_ohm: 10k; Value_Code: 10k0; Power_W: 100mW; Value2: 0.1W; VDC_V: 75V; TempCo: 100 ppm/C; SizeArea_mm2: 1.28; SizeX_mm: 1.6; SizeY_mm: 0.8; SizeZ_mm: 1; EIA_Code: E96; U/M: EA; AEC Category: Q200
RT1-RT3 = B59751B0120A070: Thermistor NTC, 50 ohm, 25%, D12.5xH16.5mm; Manufacturer: TDK; Tolerance_%: 25; TaMin_C: -40; TaMax_C: 125; U/M: EA
TP1 TP14 = CMP-0055137-1: Test Point, Miniature, Red, TH; Manufacturer: Keystone; CNHeader: FALSE; ContactFinish: Silver; CT: TRUE; Green_Lifecycle: Active; Green_REACh: Passed
TP2 TP4 TP7 TP10-TP12 = CMP-0055140-1: Test Point, Miniature, Orange, TH; Manufacturer: Keystone; CNHeader: FALSE; Green_Lifecycle: Active; Green_REACh: Passed; ContactFinish: Silver; CT: TRUE
TP3 TP6 TP8 = CMP-0055139-1: Test Point, Miniature, White, TH; Manufacturer: Keystone; CNHeader: FALSE; Green_Lifecycle: Active; Green_REACh: Passed; ContactFinish: Silver; CT: TRUE
TP5 TP13 TP15 = CMP-0055138-1: Test Point, Miniature, Black, TH; Manufacturer: Keystone; CNHeader: FALSE; Green_Lifecycle: Active; Green_REACh: Passed; ContactFinish: Silver; CT: TRUE
TP9 = CMP-0055141-1: Test Point, Miniature, Yellow, TH; Manufacturer: Keystone; CNHeader: FALSE; Green_Lifecycle: Active; Green_REACh: Passed; ContactFinish: Silver; CT: TRUE

## Sheet Power Supply and Protection-Pg3.SchDoc
size 431 x 279 mm; Date: Not shown in title block; ApprovedBy: Not shown in title block; CheckedBy: Not shown in title block; Author: Not shown in title block; CompanyName: Not shown in title block; DrawnBy: Avinash; Engineer: Not shown in title block; Organization: Not shown in title block; Address1: Not shown in title block; Address2: Not shown in title block; Address3: Not shown in title block; Address4: Not shown in title block; DocumentNumber: 1; Revision: Use project parameter SCH_Rev; SheetNumber: 3; SheetTotal: 7; PageSetup: Record=PageOptions¦CenterHorizontal=True¦CenterVertical=True¦PrintScale=1.00¦XCorrection=1.00¦YCorrection=1.00¦PrintKind=0¦BorderSize=5000000¦LeftOffset=0¦BottomOffset=0¦Orientation=2¦PaperLength=1000¦PaperWidth=1000¦Scale=100¦PaperSource=15¦PrintQuality=600¦MediaType=1¦DitherType=10¦PaperKind=Letter¦PrintScaleMode=1
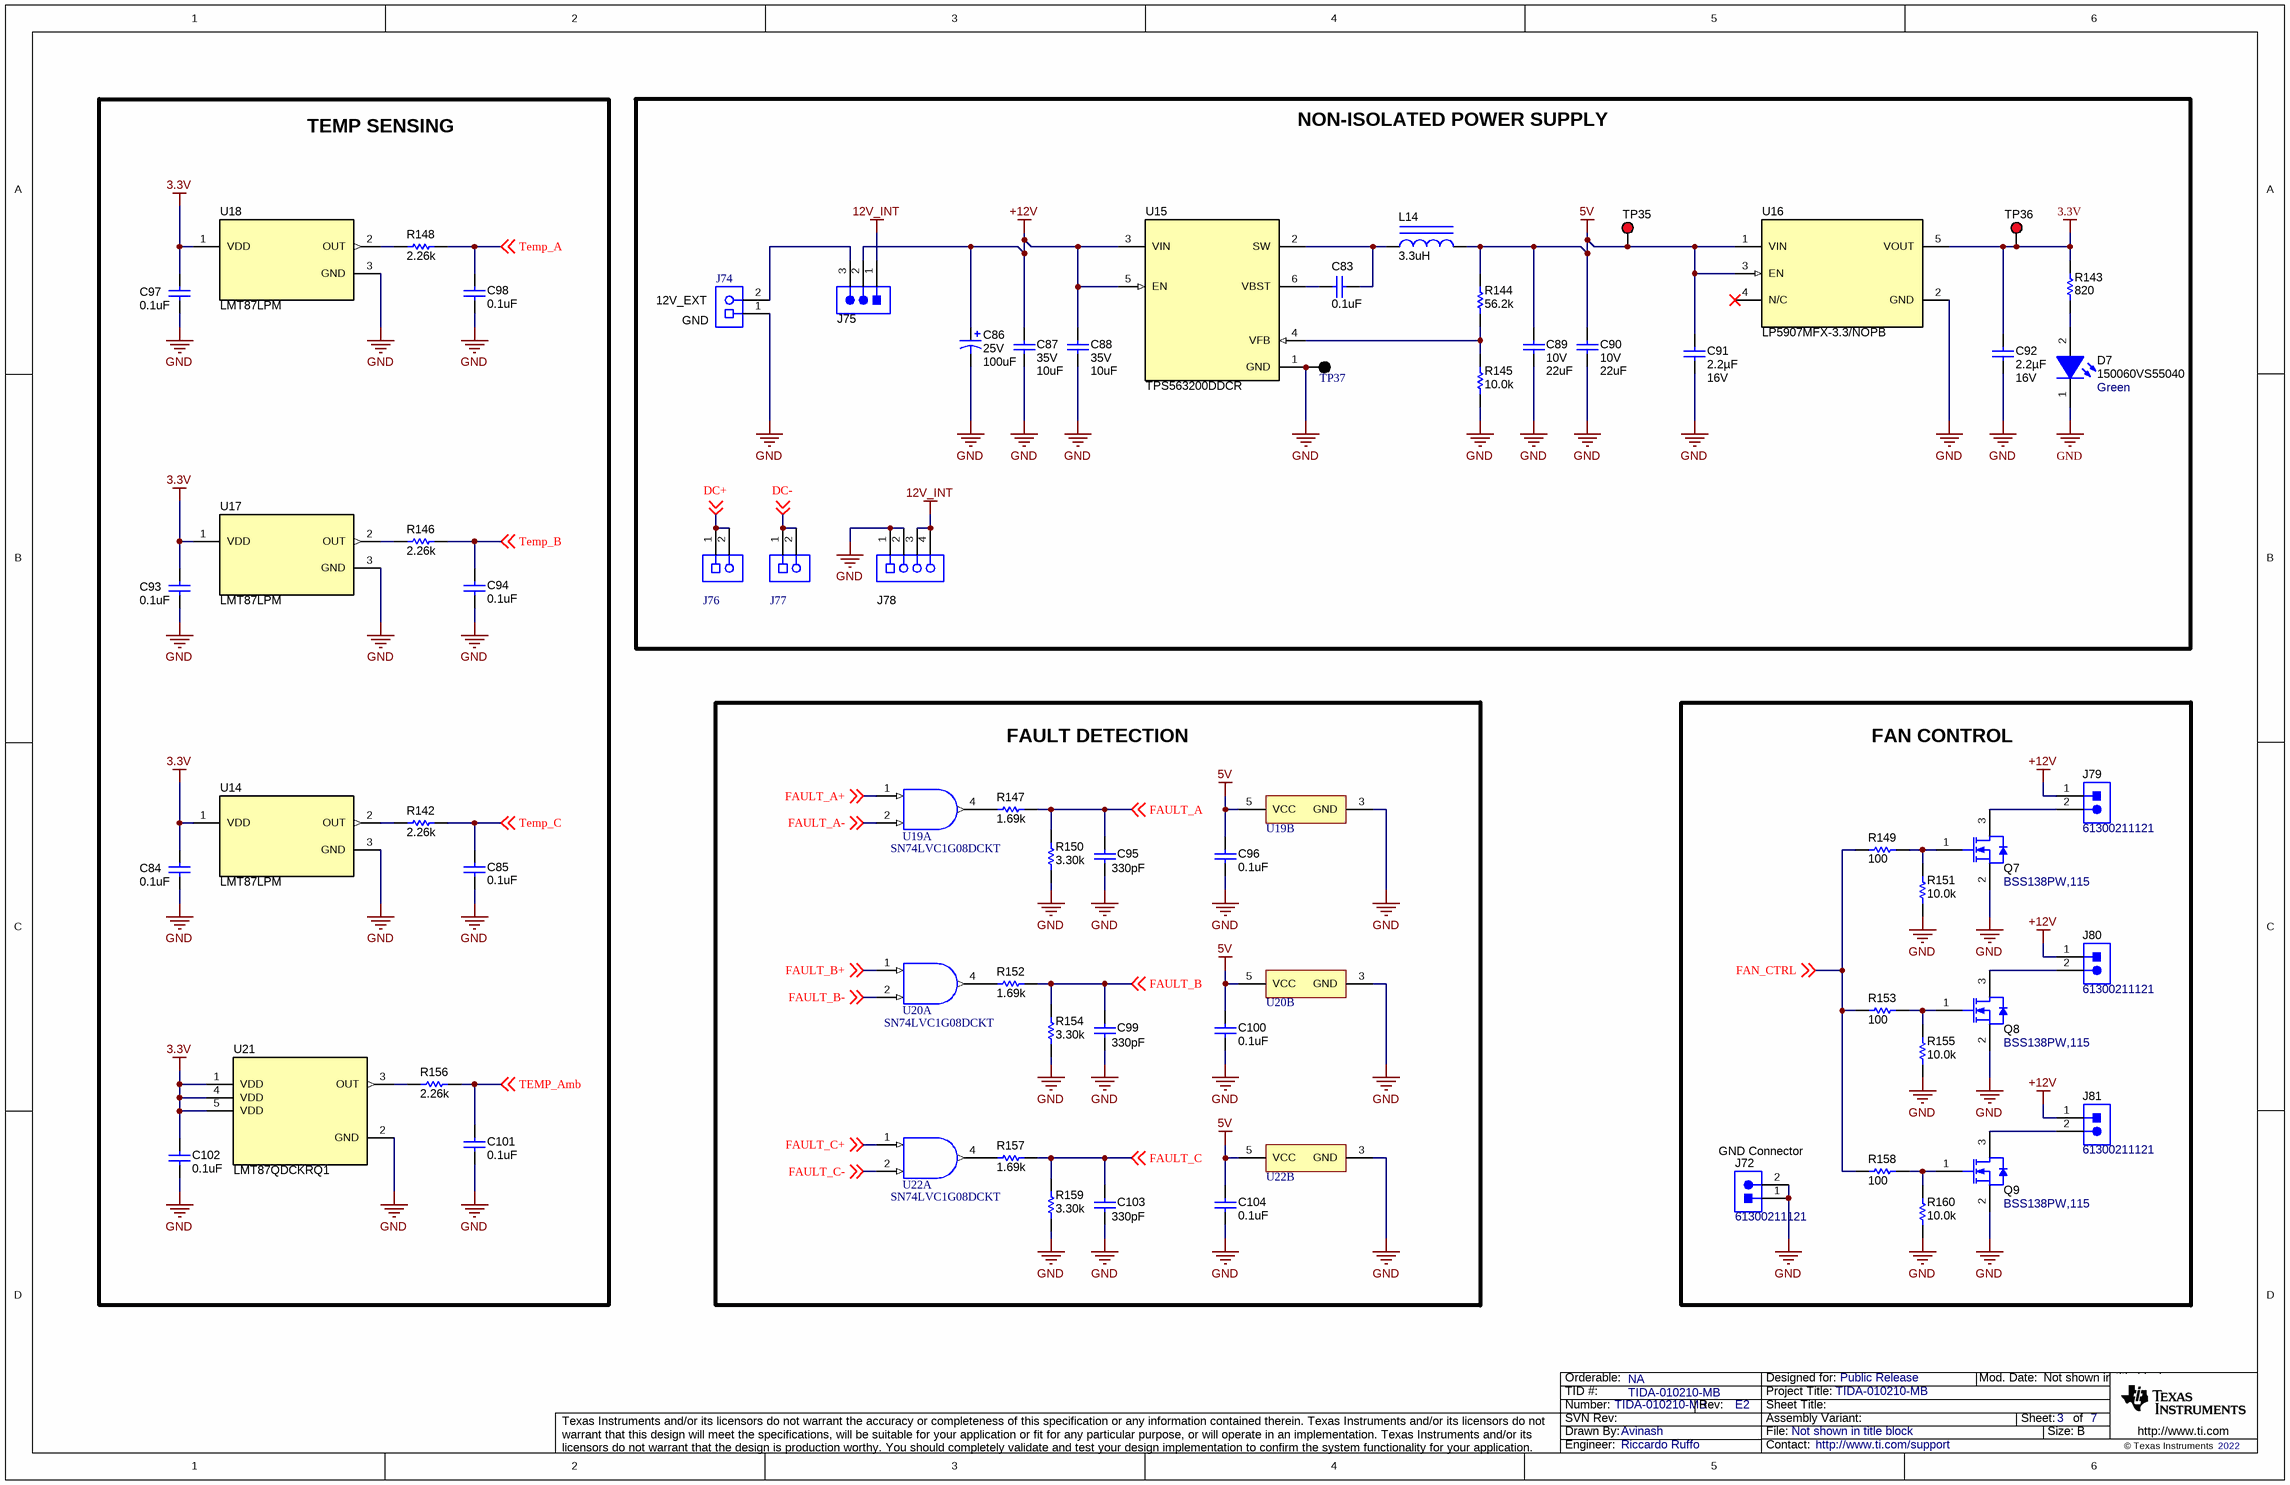
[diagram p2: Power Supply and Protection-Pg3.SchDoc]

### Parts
C83  ValueDisplayed: 0.1uF  [0603]  (hidden comment: C0603X104K3RACTU)
C84  ValueDisplayed: 0.1uF  [0603]  (hidden comment: C0603X104K3RACTU)
C85  ValueDisplayed: 0.1uF  [0603]  (hidden comment: C0603X104K3RACTU)
C86  VDC_V: 25V  ValueDisplayed: 100uF  [CAPPR250W50D630H1120]  (hidden comment: EEU-EB1E101S)
C87  VDC_V: 35V  ValueDisplayed: 10uF  [1206_190]  (hidden comment: CGA5L1X7R1V106K160AC)
C88  VDC_V: 35V  ValueDisplayed: 10uF  [1206_190]  (hidden comment: CGA5L1X7R1V106K160AC)
C89  VDC_V: 10V  ValueDisplayed: 22uF  [1206_180]  (hidden comment: GRM31CR71A226KE15L)
C90  VDC_V: 10V  ValueDisplayed: 22uF  [1206_180]  (hidden comment: GRM31CR71A226KE15L)
C91  Cap_F: 2.2µF  VDC_V: 16V  [0603]  (hidden comment: CC0603KRX7R7BB225)
C92  Cap_F: 2.2µF  VDC_V: 16V  [0603]  (hidden comment: CC0603KRX7R7BB225)
C93  ValueDisplayed: 0.1uF  [0603]  (hidden comment: C0603X104K3RACTU)
C94  ValueDisplayed: 0.1uF  [0603]  (hidden comment: C0603X104K3RACTU)
C95  ValueDisplayed: 330pF  [0603]  (hidden comment: 06035A331JAT2A)
C96  ValueDisplayed: 0.1uF  [0603]  (hidden comment: C0603X104K3RACTU)
C97  ValueDisplayed: 0.1uF  [0603]  (hidden comment: C0603X104K3RACTU)
C98  ValueDisplayed: 0.1uF  [0603]  (hidden comment: C0603X104K3RACTU)
C99  ValueDisplayed: 330pF  [0603]  (hidden comment: 06035A331JAT2A)
C100  ValueDisplayed: 0.1uF  [0603]  (hidden comment: C0603X104K3RACTU)
C101  ValueDisplayed: 0.1uF  [0603]  (hidden comment: C0603X104K3RACTU)
C102  ValueDisplayed: 0.1uF  [0603]  (hidden comment: C0603X104K3RACTU)
C103  ValueDisplayed: 330pF  [0603]  (hidden comment: 06035A331JAT2A)
C104  ValueDisplayed: 0.1uF  [0603]  (hidden comment: C0603X104K3RACTU)
D7  150060VS55040  value Green  [WL-SMCD-0603]
J72  61300211121  [WURTH_61300211121]
J74  691214110002  [Wurth_691214110002]  (value not drawn)
J75  61300311121  [WURTH_61300311121]  (value not drawn)
J76  310-13-102-41-001000  [Mill-max_310-13-102-41-001000]  (value not drawn)
J77  310-13-102-41-001000  [Mill-max_310-13-102-41-001000]  (value not drawn)
J78  310-13-104-41-001000  [Mill-max_310-13-104-41-001000]  (value not drawn)
J79  61300211121  [WURTH_61300211121]
J80  61300211121  [WURTH_61300211121]
J81  61300211121  [WURTH_61300211121]
L14  ValueDisplayed: 3.3uH  [XAL4030]  (hidden comment: XAL4030-332MEB)
Q7  BSS138PW,115  [SOT-323]
Q8  BSS138PW,115  [SOT-323]
Q9  BSS138PW,115  [SOT-323]
R142  ValueDisplayed: 2.26k  [0603]  (hidden comment: RC0603FR-072K26L)
R143  ValueDisplayed: 820  [0603]  (hidden comment: RC0603FR-07820RL)
R144  ValueDisplayed: 56.2k  [0603]  (hidden comment: RC0603FR-0756K2L)
R145  ValueDisplayed: 10.0k  [0603]  (hidden comment: ERJ-3EKF1002V)
R146  ValueDisplayed: 2.26k  [0603]  (hidden comment: RC0603FR-072K26L)
R147  ValueDisplayed: 1.69k  [0603]  (hidden comment: RC0603FR-071K69L)
R148  ValueDisplayed: 2.26k  [0603]  (hidden comment: RC0603FR-072K26L)
R149  ValueDisplayed: 100  [0603]  (hidden comment: ESR03EZPJ101)
R150  ValueDisplayed: 3.30k  [0603]  (hidden comment: RC0603FR-073K3L)
R151  ValueDisplayed: 10.0k  [0603]  (hidden comment: ERJ-3EKF1002V)
R152  ValueDisplayed: 1.69k  [0603]  (hidden comment: RC0603FR-071K69L)
R153  ValueDisplayed: 100  [0603]  (hidden comment: ESR03EZPJ101)
R154  ValueDisplayed: 3.30k  [0603]  (hidden comment: RC0603FR-073K3L)
R155  ValueDisplayed: 10.0k  [0603]  (hidden comment: ERJ-3EKF1002V)
R156  ValueDisplayed: 2.26k  [0603]  (hidden comment: RC0603FR-072K26L)
R157  ValueDisplayed: 1.69k  [0603]  (hidden comment: RC0603FR-071K69L)
R158  ValueDisplayed: 100  [0603]  (hidden comment: ESR03EZPJ101)
R159  ValueDisplayed: 3.30k  [0603]  (hidden comment: RC0603FR-073K3L)
R160  ValueDisplayed: 10.0k  [0603]  (hidden comment: ERJ-3EKF1002V)
TP35  5000  [Keystone5000]  (value not drawn)
TP36  5000  [Keystone5000]  (value not drawn)
TP37  5001  [Keystone5001]  (value not drawn)
U14  LMT87LPM  [LP0003A]
U15  TPS563200DDCR  [DDC0006A_N]
U16  LP5907MFX-3.3/NOPB  [DBV0005A_N]
U17  LMT87LPM  [LP0003A]
U18  LMT87LPM  [LP0003A]
U19  SN74LVC1G08DCKT  [DCK0005A_N]  (parts A,B of 2)
U20  SN74LVC1G08DCKT  [DCK0005A_N]  (parts A,B of 2)
U21  LMT87QDCKRQ1  [DCK0005A_N]
U22  SN74LVC1G08DCKT  [DCK0005A_N]  (parts A,B of 2)

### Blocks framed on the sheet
TEMP SENSING: C84 C85 C93 C94 C97 C98 C101 C102 R142 R146 R148 R156 U14 U17 U18 U21
NON-ISOLATED POWER SUPPLY: C83 C86-C92 D7 J74-J78 L14 R143-R145 TP35-TP37 U15 U16
FAULT DETECTION: C95 C96 C99 C100 C103 C104 R147 R150 R152 R154 R157 R159 U19 U20 U22
FAN CONTROL: J72 J79-J81 Q7-Q9 R149 R151 R153 R155 R158 R160

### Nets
3.3V: C84.2 C92.1 C93.2 C97.2 C102.2 R143.1 TP36.1 U14.1(VDD) U16.5(VOUT) U17.1(VDD) U18.1(VDD) U21.1(VDD) U21.4(VDD) U21.5(VDD)
5V: C89.1 C90.1 C91.1 C96.2 C100.2 C104.2 L14.2 R144.2 TP35.1 U16.1(VIN) U16.3(EN) U19.5(VCC) U20.5(VCC) U22.5(VCC)
12V_INT: J75.1 J78.3 J78.4
+12V: C86.1(+) C87.1 C88.1 J75.2 J79.1 J80.1 J81.1 U15.3(VIN) U15.5(EN)
GND: C84.1 C85.1 C86.2(-) C87.2 C88.2 C89.2 C90.2 C91.2 C92.2 C93.1 C94.1 C95.2 C96.1 C97.1 C98.1 C99.2 C100.1 C101.1 C102.1 C103.2 C104.1 D7.1(K) J72.1 J72.2 J74.1 J78.1 J78.2 Q7.2(S) Q8.2(S) Q9.2(S) R145.1 R150.1 R151.1 R154.1 R155.1 R159.1 R160.1 TP37.1 U14.3(GND) U15.1(GND) U16.2(GND) U17.3(GND) U18.3(GND) U19.3(GND) U20.3(GND) U21.2(GND) U22.3(GND)
DC+: J76.1 J76.2 ; off-sheet DC+
DC-: J77.1 J77.2 ; off-sheet DC-
FAN_CTRL: R149.1 R153.1 R158.1 ; off-sheet FAN_CTRL
FAULT_A: C95.1 R147.2 R150.2 ; off-sheet FAULT_A
FAULT_A+: U19.1(A) ; off-sheet FAULT_A+
FAULT_A-: U19.2(B) ; off-sheet FAULT_A-
FAULT_B: C99.1 R152.2 R154.2 ; off-sheet FAULT_B
FAULT_B+: U20.1(A) ; off-sheet FAULT_B+
FAULT_B-: U20.2(B) ; off-sheet FAULT_B-
FAULT_C: C103.1 R157.2 R159.2 ; off-sheet FAULT_C
FAULT_C+: U22.1(A) ; off-sheet FAULT_C+
FAULT_C-: U22.2(B) ; off-sheet FAULT_C-
Temp_A: C98.2 R148.2 ; off-sheet Temp_A
TEMP_Amb: C101.2 R156.2 ; off-sheet TEMP_Amb
Temp_B: C94.2 R146.2 ; off-sheet Temp_B
Temp_C: C85.2 R142.2 ; off-sheet Temp_C
NetC83_1: C83.1 L14.1 U15.2(SW)
NetC83_2: C83.2 U15.6(VBST)
NetD7_2: D7.2(A) R143.2
NetJ74_2: J74.2 J75.3
NetJ79_2: J79.2 Q7.3(D)
NetJ80_2: J80.2 Q8.3(D)
NetJ81_2: J81.2 Q9.3(D)
NetQ7_1: Q7.1(G) R149.2 R151.2
NetQ8_1: Q8.1(G) R153.2 R155.2
NetQ9_1: Q9.1(G) R158.2 R160.2
NetR142_1: R142.1 U14.2(OUT)
NetR144_1: R144.1 R145.2 U15.4(VFB)
NetR146_1: R146.1 U17.2(OUT)
NetR147_1: R147.1 U19.4(Y)
NetR148_1: R148.1 U18.2(OUT)
NetR152_1: R152.1 U20.4(Y)
NetR156_1: R156.1 U21.3(OUT)
NetR157_1: R157.1 U22.4(Y)

Not connected (* = marked no-connect by the designer): U16 4(N/C)*

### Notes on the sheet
- (near J74) 12V_EXT
- (near J74) GND
- (near J72) GND Connector

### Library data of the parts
C83-C85 C93 C94 C96-C98 C100-C102 C104 = CMP-0006979-5: CAP, CERM, 0.1 uF, 25 V, +/- 10%, X7R, 0603; Manufacturer: Kemet; Polarized: N; Value: 0.1uF; U/M: EA; Cap_F: 100nF; Value1: Unknown; VDC_V: 25V; TaMin_C: -55°C; TaMax_C: 125°C; AEC Category: Q200; SizeArea_mm2: 1.28; SizeAreaWB_mm2: 4.68; SizeX_mm: 1.6; SizeY_mm: 0.8; SizeZ_mm: 1
C86 = CMP-0010333-1: CAP, AL, 100 uF, 25 V, +/- 20%, TH; Manufacturer: Panasonic; TaMin_C: -40°C; Polarized: Y; SizeAreaWB_mm2: 68.89; Value1: Unknown; U/M: EA; Value: 100uF; TaMax_C: 105°C; SizeZ_mm: 11.2; SizeX_mm: 6.3; Cap_Case: Radial 6.3x11.2; SizeArea_mm2: 39.69; CompType: Capacitor; AEC Qualified: N; Cap_F: 100µF; IRMS_A: 95mA; AEC Category: Q200
C87 C88 = CMP-0008772-2: as C12 on sheet Power Stage-Pg2
C89 C90 = CMP-0008959-2: CAP, CERM, 22 uF, 10 V, +/- 10%, X7R, 1206; Manufacturer: MuRata; TaMin_C: -55°C; Polarized: N; SizeAreaWB_mm2: 10.92; Value1: Unknown; U/M: EA; Value: 22uF; TaMax_C: 125°C; SizeZ_mm: 1.8; SizeX_mm: 3.2; SizeY_mm: 1.6; Cap_Case: 1206; SizeArea_mm2: 5.12; Cap_F: 22µF; AEC Category: Q200
C91 C92 = CMP-0079605-1: CAP, CERM, 2.2 µF, 16 V,+/- 10%, X7R, 0603; Manufacturer: Yageo America; TaMin_C: -55°C; Polarized: N; SizeAreaWB_mm2: 4.68; U/M: EA; Value: 2.2uF; TaMax_C: 125°C; SizeZ_mm: 1; SizeX_mm: 1.6; SizeY_mm: 0.8; SizeArea_mm2: 1.28; AEC Category: Q200
C95 C99 C103 = CMP-0006784-4: CAP, CERM, 330 pF, 50 V, +/- 5%, C0G/NP0, 0603; Manufacturer: AVX; TaMin_C: -55°C; ESR_ohm: 0.071; Polarized: N; SizeAreaWB_mm2: 4.68; Value1: 0.071 ohm; U/M: EA; Value: 330pF; TaMax_C: 125°C; SizeZ_mm: 1; SizeX_mm: 1.6; SizeY_mm: 0.8; Value2: 50V; SizeArea_mm2: 1.28; AEC Category: Q200
D7 = CMP-0081648-2: LED, Green, SMD; Manufacturer: Wurth Elektronik; Io_A: 20mA; Power_TotalModule: 48mW; Vr_V: 5V; SizeAreaWB_mm2: 4.68; Tjmax_C: 115°C; Value1: 0.048W; Angle: 140; SizeZ_mm: 0.5; SizeX_mm: 1.6; SizeY_mm: 0.8; Ir_A: 10µA; Vf_V: 2V; SizeArea_mm2: 1.28; Type: AlInGaP
J72 J79-J81 = CMP-0054794-2: Header, 2.54 mm, 2x1, Gold, TH; Manufacturer: Wurth Elektronik; Green_Lifecycle: Active; Green_REACh: Passed; Cert_UL: Y; Gender: Male; Pitch_mm: 2.54; Row_Count: 1; Shrouded: N
J74 = CMP-0054825-2: Terminal Block, 3.5mm, 2x1, Tin, TH; Manufacturer: Wurth Elektronik; Pitch_mm: 3.5; CT: TRUE; CNHeader: FALSE; Voltage_V: 300V; Gender: Female; Cert_UL: Y; Row_Count: 1; Current_A: 10A
J75 = CMP-0054796-2: Header, 2.54 mm, 3x1, Gold, TH; Manufacturer: Wurth Elektronik; Pitch_mm: 2.54; Green_Lifecycle: Active; Cert_UL: Y; Shrouded: N; Green_REACh: Passed; Gender: Male; Row_Count: 1
J76 J77 = CMP-0055073-1: Socket Strip, 100mil, 2x1, Gold, TH; Manufacturer: Mill-Max; CT: TRUE; CNHeader: FALSE
J78 = CMP-0084081-1: Receptacle, 2.54mm, 4x1, TH; Manufacturer: Mill-Max; Pitch_mm: 2.54; CompType: Socket Strip; ContactFinish: Gold; Gender: Female; Row_Count: 1
L14 = CMP-0060989-1: Inductor, Shielded, Composite, 3.3 uH, 5.5 A, 0.026 ohm, SMD; Manufacturer: Coilcraft; Isat: 5.5A @ 30% inductance drop; Irms: 6.6A @ 40C rise; Green_Lifecycle: Not Set; SizeAreaWB_mm2: 25; DCR_ohm: 0.026; Green_REACh: Incomplete; Value: 3.3uH; Imax_A: 5.5A; SizeZ_mm: 3.1; SizeX_mm: 4; SizeArea_mm2: 16; Ind_H: 3.3µH; AEC Category: Q200
Q7-Q9 = CMP-0000790-2: as Q1 on sheet Power Stage-Pg2
R142 R146 R148 R156 = CMP-0022985-5: RES, 2.26 k, 1%, 0.1 W, 0603; Manufacturer: Yageo; Power_W: 100mW; TempCo: 100 ppm/C; Value_Code: 2k26; Value: 2.26k; EIA_Code: E96; SizeX_mm: 1.6; SizeY_mm: 0.8; SizeZ_mm: 1; Value2: 0.1W; SizeArea_mm2: 1.28; AEC Qualified: N; VDC_V: 75V; AEC Category: Q200; SizeAreaWB_mm2: 4.68
R143 = CMP-0023288-5: RES, 820, 1%, 0.1 W, 0603; Manufacturer: Yageo; Value: 820; Value_Code: 820R; Power_W: 100mW; Value2: 0.1W; VDC_V: 75V; TempCo: 100 ppm/C; SizeArea_mm2: 1.28; SizeX_mm: 1.6; SizeY_mm: 0.8; SizeZ_mm: 1; AEC Category: Q200; AEC Qualified: N; SizeAreaWB_mm2: 4.68
R144 = CMP-0023186-5: RES, 56.2 k, 1%, 0.1 W, 0603; Manufacturer: Yageo; Power_W: 100mW; TempCo: 100 ppm/C; Value_Code: 56k2; Value: 56.2k; EIA_Code: E96; SizeX_mm: 1.6; SizeY_mm: 0.8; SizeZ_mm: 1; Value2: 0.1W; SizeArea_mm2: 1.28; AEC Qualified: N; VDC_V: 75V; AEC Category: Q200; SizeAreaWB_mm2: 4.68
R145 R151 R155 R160 = CMP-0022684-3: as R27 on sheet Power Stage-Pg2
R147 R152 R157 = CMP-0022886-5: RES, 1.69 k, 1%, 0.1 W, 0603; Manufacturer: Yageo; Power_W: 100mW; TempCo: 100 ppm/C; Value_Code: 1k69; Value: 1.69k; EIA_Code: E96; SizeX_mm: 1.6; SizeY_mm: 0.8; SizeZ_mm: 1; Value2: 0.1W; SizeArea_mm2: 1.28; AEC Qualified: N; VDC_V: 75V; AEC Category: Q200; SizeAreaWB_mm2: 4.68
R149 R153 R158 = CMP-0025882-3: as R21 on sheet Power Stage-Pg2
R150 R154 R159 = CMP-0023081-5: RES, 3.30 k, 1%, 0.1 W, 0603; Manufacturer: Yageo; Power_W: 100mW; TempCo: 100 ppm/C; Value_Code: 3k30; Value: 3.30k; Res_ohm: 3.3k; SizeX_mm: 1.6; SizeY_mm: 0.8; SizeZ_mm: 1; Value2: 0.1W; SizeArea_mm2: 1.28; AEC Qualified: N; VDC_V: 75V; AEC Category: Q200; SizeAreaWB_mm2: 4.68
TP35 TP36 = CMP-0055137-1: as TP1 on sheet Power Stage-Pg2
TP37 = CMP-0055138-1: as TP5 on sheet Power Stage-Pg2
U14 U17 U18 = CMP-0076507-3: 2.7V-Capable, 10 uA Analog Output Temperature Sensor in SC70 and TO-92, LP0003A (TO-92-3); Manufacturer: Texas Instruments; SizeArea_mm2: 18.4; SizeAreaWB_mm2: 39.76; SizeX_mm: 3.68; SizeY_mm: 5.0; SizeZ_mm: 9.33; CompType: IC; AEC Category: Q200; AEC Qualified: N; Rating: Catalog
U15 = CMP-0067070-2: 17 V Input, 3A Synchronous Step-Down Regulator in SOT-23 with Advanced Eco-mode(TM), DDC0006A (SOT-23-T-6); Alternate PartNumber: TPS563200DDCT; Alternate Manufacturer: Texas Instruments; Green_Lifecycle: Active; SizeAreaWB_mm2: 10.4675; Green_REACh: Passed; U/M: EA; SizeZ_mm: 0.87; SizeX_mm: 1.65; SizeY_mm: 2.95; SizeArea_mm2: 4.8675; CompType: IC
U16 = CMP-0066020-1: 250-mA Ultra-Low-Noise, Low-IQ LDO, DBV0005A (SOT-23-5); Alternate Manufacturer: Texas Instruments; Green_Lifecycle: Active; SizeAreaWB_mm2: 14.82; Green_REACh: Passed; U/M: EA; SizeZ_mm: 1.45; SizeX_mm: 2.8; SizeY_mm: 2.9; SizeArea_mm2: 8.12; CompType: IC
U19 U20 U22 = CMP-0051559-1: Single 2-Input Positive-AND Gate, DCK0005A, SMALL T&R; Manufacturer: Texas Instruments; ICC @ Nom Voltage(Max)(mA): 0.01; VCC(Min)(V): 1.65; F @ Nom Voltage(Max)(Mhz): 150; Rating: Catalog; Output Type: CMOS; Input Type: CMOS/TTL; Voltage(Nom)(V): 1.8,2.5,3.3,5; Schmitt Trigger: No; tpd @ Nom Voltage(Max)(ns): 4.5,6,4,5; Bits(#): 1; VCC(Max)(V): 5.5; Technology Family: LVC; Output Drive (IOL/IOH)(Max)(mA): 32/-32; Gate Type: AND; Logic: True
U21 = CMP-0066236-2: Automotive Grade, 2.7V-Capable, 10 uA Analog Output Temperature Sensor, DCK0005A (SOT-SC70-5); Alternate PartNumber: LMT87QDCKTQ1; Manufacturer: Texas Instruments; SizeArea_mm2: 4.2; SizeAreaWB_mm2: 9.3; SizeX_mm: 2.1; SizeY_mm: 2.0; SizeZ_mm: 1.1; CompType: IC; AEC Category: Q200; AEC Qualified: Y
